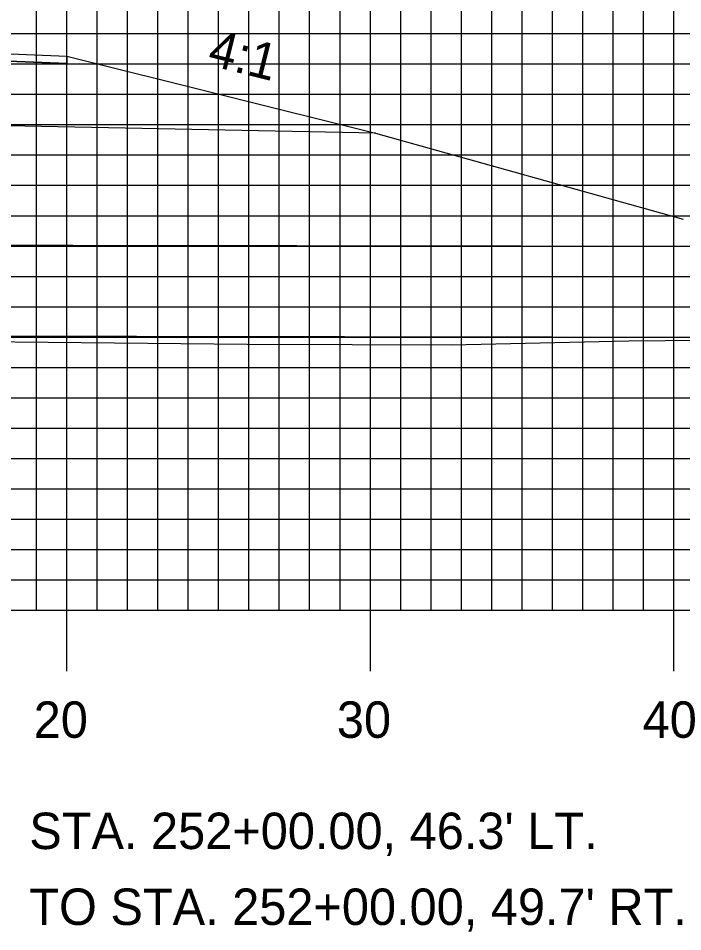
# Model space of a CAD drawing. Extents: x 1804290 to 1804634, y 442591 to 442811.
# Drawn here: x 1804474.57 to 1804496.46, y 442643.08 to 442673.17 of the extents above; entities that cross this region are included whole.
import ezdxf

# ---------------------------------------------------------------- set-up
doc = ezdxf.new("R2010")
doc.units = 0
for name, color, linetype in [('ANNOTATION', 7, 'Continuous'), ('D_Drainage_Culvert', 7, 'Continuous'), ('D_Roadway_Edge_Shoulder', 7, 'Continuous'), ('D_Roadway_SubGrade', 7, 'Continuous'), ('D_Text_Standard', 7, 'Continuous'), ('H_V ANNOTATION', 7, 'Continuous'), ('MAJOR', 7, 'Continuous'), ('MINOR', 7, 'Continuous'), ('S_Roadway_Centerline', 7, 'Continuous')]:
    doc.layers.add(name, color=color, linetype=linetype)

msp = doc.modelspace()

# ---------------------------------------------------------------- linework, layer by layer
at = {"layer": 'ANNOTATION'}
msp.add_line((1804486.341, 442669.381), (1804496.471, 442666.551), dxfattribs=at)
at = {"layer": 'D_Drainage_Culvert'}
msp.add_line((1804407.504, 442662.794), (1804505.89, 442662.656), dxfattribs=at)
msp.add_lwpolyline([(1804409.888, 442662.791), (1804409.893, 442665.791), (1804505.893, 442665.645), (1804505.888, 442662.645)], close=True, dxfattribs=at)
at = {"layer": 'D_Roadway_Edge_Shoulder'}
msp.add_lwpolyline([(1804468.167, 442672.244), (1804476.167, 442671.924), (1804476.167, 442671.674), (1804468.167, 442671.994)], close=True, dxfattribs=at)
at = {"layer": 'D_Roadway_SubGrade'}
msp.add_lwpolyline([(1804444.167, 442669.168), (1804425.993, 442668.805), (1804436.167, 442671.348), (1804436.167, 442671.098), (1804444.167, 442671.418), (1804456.167, 442671.706), (1804468.167, 442671.994), (1804476.167, 442671.674), (1804476.167, 442671.924), (1804486.341, 442669.381), (1804468.167, 442669.744), (1804456.167, 442669.456)], close=True, dxfattribs=at)
at = {"layer": 'MAJOR'}
for p, q in [((1804476.167, 442653.665), (1804476.167, 442678.665)), ((1804486.167, 442653.665), (1804486.167, 442678.665)), ((1804496.167, 442653.665), (1804496.167, 442678.665)), ((1804316.167, 442668.665), (1804596.167, 442668.665)), ((1804316.167, 442663.665), (1804596.167, 442663.665)), ((1804316.167, 442658.665), (1804596.167, 442658.665)), ((1804316.167, 442653.665), (1804596.167, 442653.665)), ((1804316.167, 442653.665), (1804596.167, 442653.665)), ((1804476.167, 442651.661), (1804476.167, 442653.665)), ((1804486.167, 442651.661), (1804486.167, 442653.665)), ((1804496.167, 442651.661), (1804496.167, 442653.665))]:
    msp.add_line(p, q, dxfattribs=at)
at = {"layer": 'MINOR'}
for p, q in [((1804475.167, 442653.665), (1804475.167, 442678.665)), ((1804477.167, 442653.665), (1804477.167, 442678.665)), ((1804478.167, 442653.665), (1804478.167, 442678.665)), ((1804479.167, 442653.665), (1804479.167, 442678.665)), ((1804480.167, 442653.665), (1804480.167, 442678.665)), ((1804481.167, 442653.665), (1804481.167, 442678.665)), ((1804482.167, 442653.665), (1804482.167, 442678.665)), ((1804483.167, 442653.665), (1804483.167, 442678.665)), ((1804484.167, 442653.665), (1804484.167, 442678.665)), ((1804485.167, 442653.665), (1804485.167, 442678.665)), ((1804487.167, 442653.665), (1804487.167, 442678.665)), ((1804488.167, 442653.665), (1804488.167, 442678.665)), ((1804489.167, 442653.665), (1804489.167, 442678.665)), ((1804490.167, 442653.665), (1804490.167, 442678.665)), ((1804491.167, 442653.665), (1804491.167, 442678.665)), ((1804492.167, 442653.665), (1804492.167, 442678.665)), ((1804493.167, 442653.665), (1804493.167, 442678.665)), ((1804494.167, 442653.665), (1804494.167, 442678.665)), ((1804495.167, 442653.665), (1804495.167, 442678.665)), ((1804316.167, 442672.665), (1804596.167, 442672.665)), ((1804316.167, 442671.665), (1804596.167, 442671.665)), ((1804316.167, 442670.665), (1804596.167, 442670.665)), ((1804316.167, 442669.665), (1804596.167, 442669.665)), ((1804316.167, 442667.665), (1804596.167, 442667.665)), ((1804316.167, 442666.665), (1804596.167, 442666.665)), ((1804316.167, 442665.665), (1804596.167, 442665.665)), ((1804316.167, 442664.665), (1804596.167, 442664.665)), ((1804316.167, 442662.665), (1804596.167, 442662.665)), ((1804316.167, 442661.665), (1804596.167, 442661.665)), ((1804316.167, 442660.665), (1804596.167, 442660.665)), ((1804316.167, 442659.665), (1804596.167, 442659.665)), ((1804316.167, 442657.665), (1804596.167, 442657.665)), ((1804316.167, 442656.665), (1804596.167, 442656.665)), ((1804316.167, 442655.665), (1804596.167, 442655.665)), ((1804316.167, 442654.665), (1804596.167, 442654.665))]:
    msp.add_line(p, q, dxfattribs=at)
at = {"layer": 'S_Roadway_Centerline'}
msp.add_lwpolyline([(1804392.455, 442662.786), (1804403.753, 442662.746), (1804414.339, 442662.882), (1804416.075, 442662.891), (1804434.951, 442662.77), (1804441.486, 442662.699), (1804450.248, 442662.785), (1804459.333, 442662.638), (1804461.991, 442662.67), (1804464.615, 442662.608), (1804482.103, 442662.436), (1804485.564, 442662.421), (1804488.839, 442662.416), (1804494.685, 442662.541), (1804511.409, 442662.696), (1804519.927, 442662.797)], dxfattribs=at)

# ---------------------------------------------------------------- texts
at = {"layer": 'ANNOTATION'}
msp.add_text('4:1', height=1.2, rotation=345.9638, dxfattribs=at).set_placement((1804480.76, 442671.638))
at = {"layer": 'D_Text_Standard'}
for s, p in [("STA. 252+00.00, 46.3' LT.", (1804474.928, 442645.801)), ("TO STA. 252+00.00, 49.7' RT.", (1804474.928, 442643.301))]:
    msp.add_text(s, height=1.2, dxfattribs=at).set_placement(p)
at = {"layer": 'H_V ANNOTATION'}
for s, p in [('20', (1804475.075, 442649.465)), ('30', (1804485.064, 442649.465)), ('40', (1804495.139, 442649.465))]:
    msp.add_text(s, height=1.2, dxfattribs=at).set_placement(p)

doc.saveas('drawing.dxf')
